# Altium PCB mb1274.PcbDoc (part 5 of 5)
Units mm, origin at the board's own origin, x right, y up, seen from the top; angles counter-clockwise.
Board outline 70 x 105 mm, 4 copper layers (Top Layer, Mid-Layer 1, Mid-Layer 2, Bottom Layer), stack 1.58 mm thick; 329 components, 271 nets, 1213 pads, 779 vias.
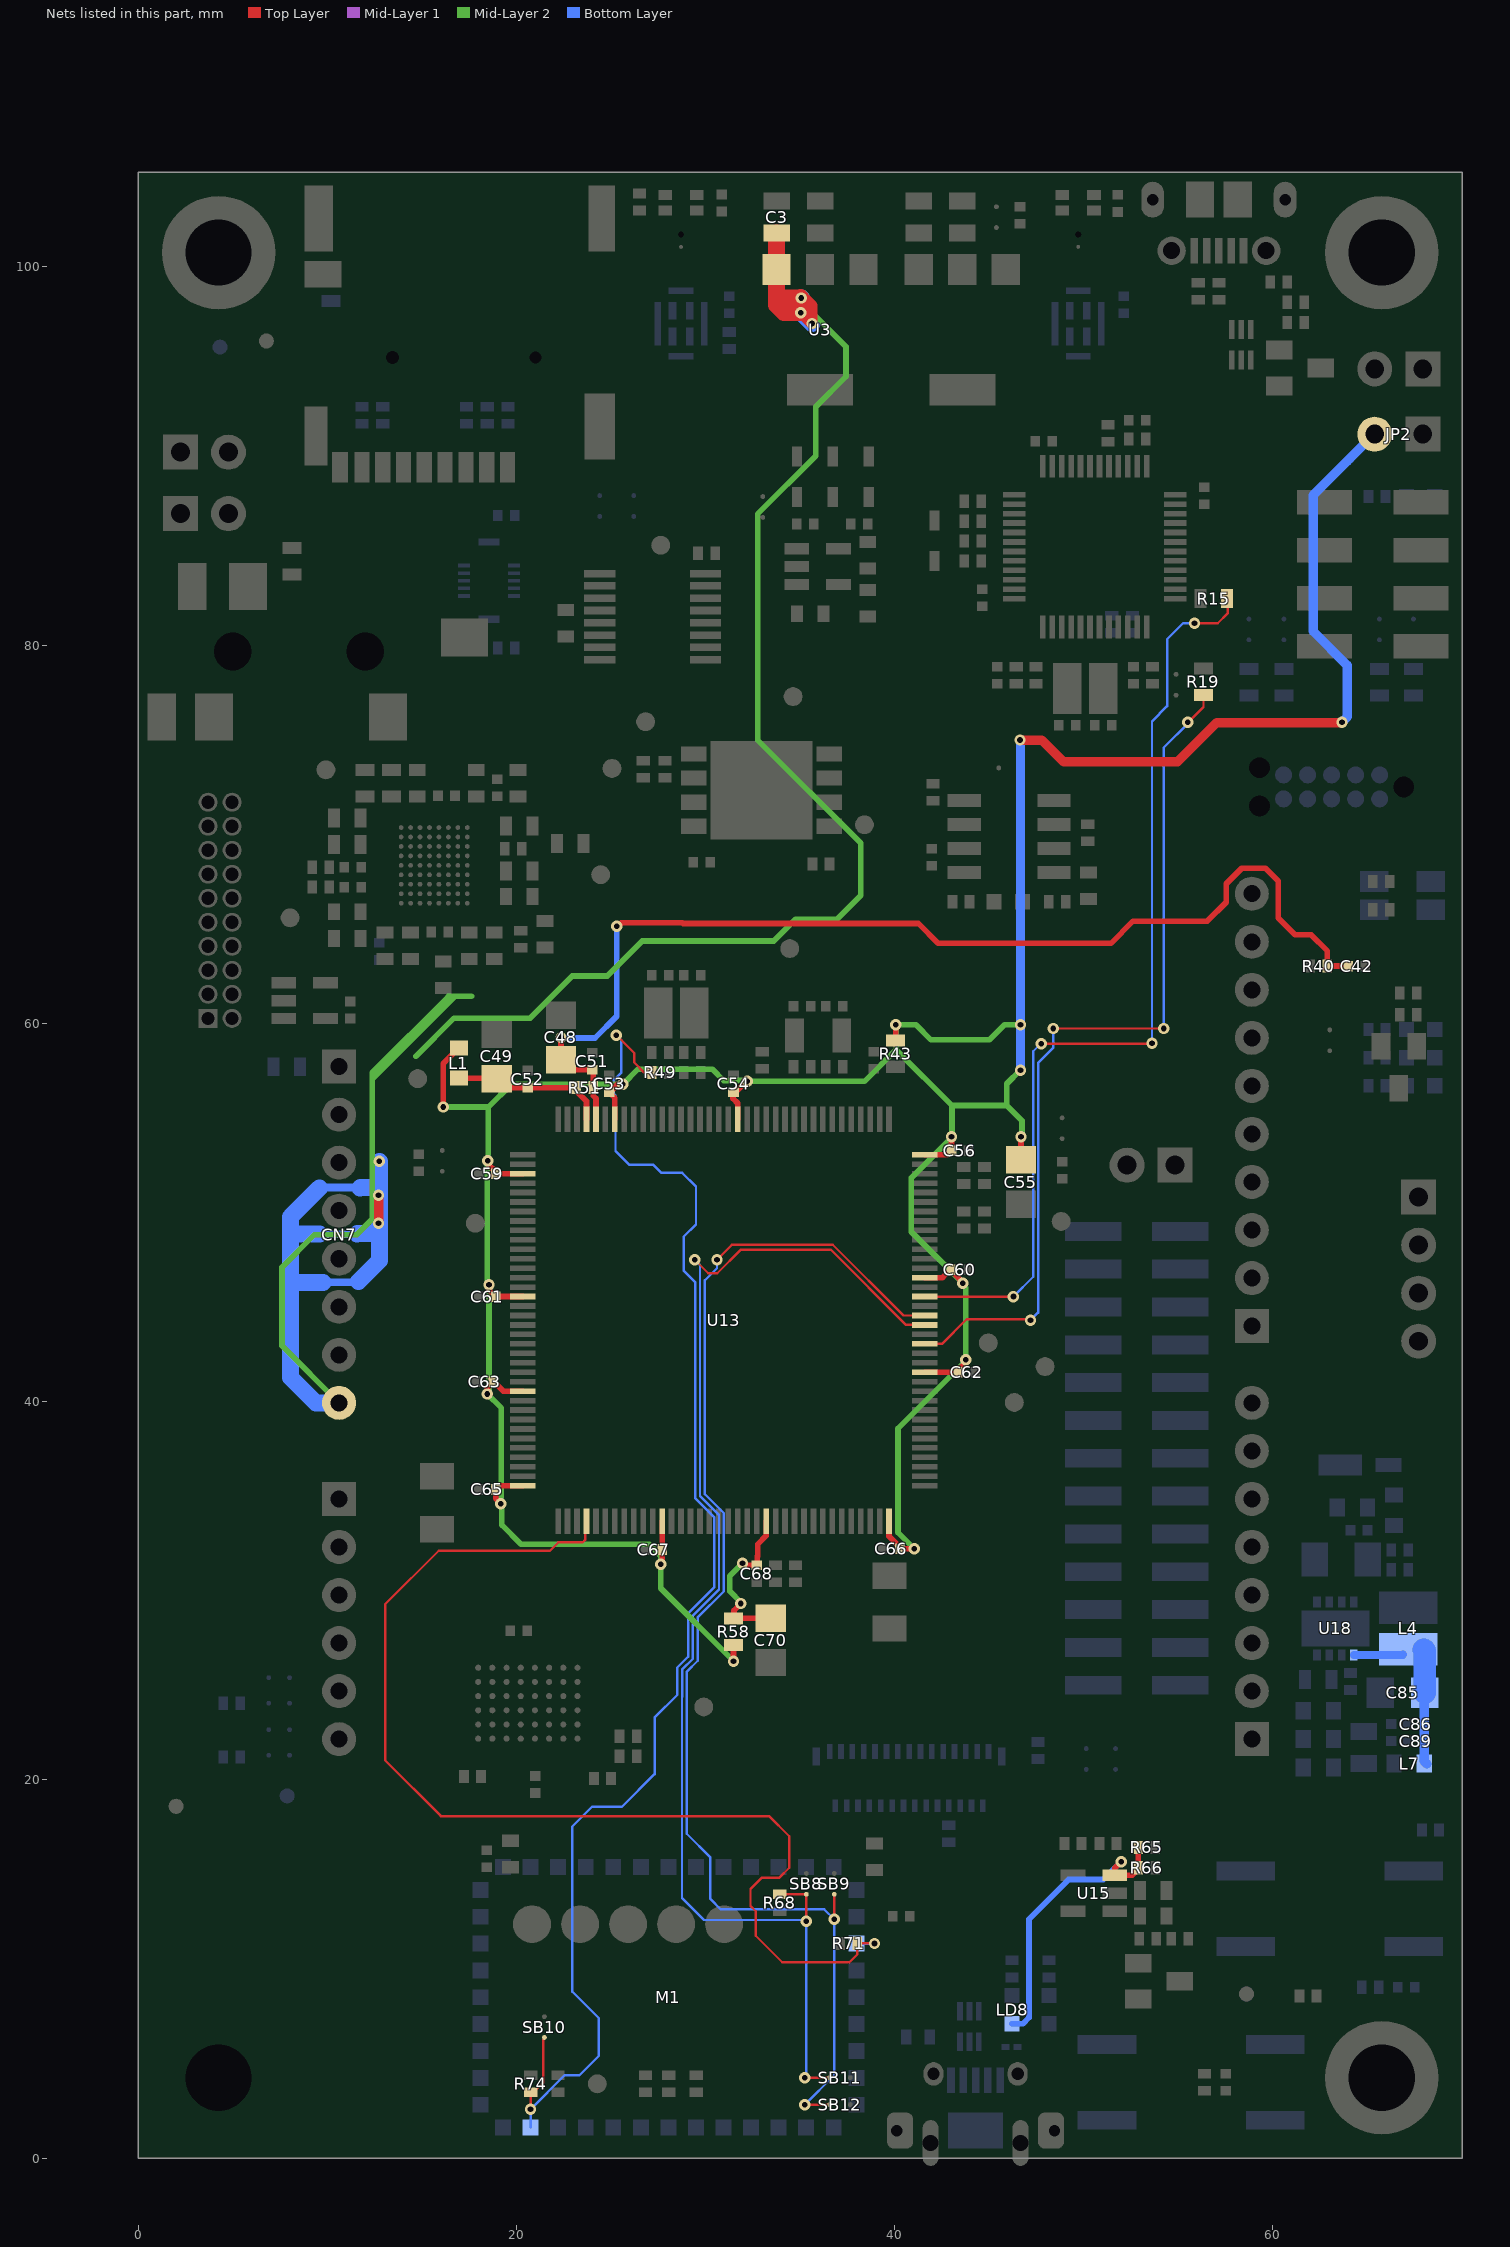
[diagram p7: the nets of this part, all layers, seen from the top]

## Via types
v1: diameter 0.6, hole 0.3, Top Layer to Bottom Layer, tented both sides, 574 vias
v2: diameter 0.4, hole 0.2, Top Layer to Bottom Layer, tented both sides, 125 vias
v3: diameter 0.8, hole 0.4, Top Layer to Bottom Layer, tented both sides, 49 vias
v4: diameter 0.3, hole 0.15, Top Layer to Bottom Layer, tented both sides, 31 vias

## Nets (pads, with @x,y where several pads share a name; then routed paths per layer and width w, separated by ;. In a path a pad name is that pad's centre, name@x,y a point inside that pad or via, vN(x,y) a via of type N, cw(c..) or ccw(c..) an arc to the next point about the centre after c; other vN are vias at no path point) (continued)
VBUS_OVRCR: LD8.2 R65.2 R66.1 U15.3 | length 15.3
  Top Layer w0.3: v1(51.975,15.675) 51.625,15.325 U15.3@51.625,14.95 52.55,14.95 R66.1@52.7,15.1 ; R66.1@52.875,15.475 R65.2@52.875,16.425
  Bottom Layer w0.3: LD8.2@46.2,7.1 46.775,7.1 47.1,7.425 47.1,12.625 49.2,14.725 51.025,14.725 v1(51.975,15.675)
VCP_RX: R19.1 U13.124 | length 46.5
  Top Layer w0.127: U13.124@41.575,43.05 42.5,43.05 43.8,44.35 47.129,44.35 v1(47.177,44.302) ; v1(48.375,59.725) v1@54.2,59.725 ; v1@55.525,75.925 56.325,76.725 R19.1@56.325,77.35
  Bottom Layer w0.127: v1(47.177,44.302) 47.579,44.704 47.579,57.904 48.375,58.7 v1(48.375,59.725) ; v1@54.225,59.625 v1(54.225,59.725) 54.225,74.575 v1@55.55,75.9
  other v1: 55.5,75.925
VCP_TX: R15.1 U13.129 | length 50.9
  Top Layer w0.127: U13.129@41.575,45.55 v1(46.275,45.55) ; v1(47.75,58.925) 53.575,58.925 v1(53.6,58.95) ; v1(55.85,81.15) 57.075,81.15 57.6,81.675 R15.1@57.6,82.55
  Bottom Layer w0.127: v1(46.275,45.55) 47.325,46.6 47.325,58.525 47.725,58.925 v1(47.75,58.925) ; v1(53.6,58.95) 53.6,75.966 54.404,76.77 54.404,80.304 55.25,81.15 v1(55.85,81.15)
VDD_MCU: C53.2 C54.2 C55.1 C56.2 C59.2 C60.2 C61.2 C62.2 C63.2 C65.2 C66.2 C67.2 JP2.2 L1.1 R43.2 R58.1 U13.17 U13.30 U13.39 U13.52 U13.62 U13.72 U13.84 U13.108 U13.121 U13.131 U13.144 | length 197.1
  Top Layer w0.3: v1(16.125,55.575) 16.125,57.875 L1.1@16.95,58.7 ; v1(18.45,40.4) 18.45,40.725 C63.2@18.775,41.05 ; v1(18.476,52.727) 18.476,52.574 18.9,52.15 C59.2@18.9,52.05 ; v1(18.55,46.175) 18.55,45.9 C61.2@18.9,45.55 ; C63.2@18.875,40.975 19.3,40.55 U13.62@20.325,40.55 ; C59.2@18.875,52.05 U13.39@20.325,52.05 ; C65.2@18.9,35.35 C65.2@18.9,35.325 ; C61.2@18.925,45.575 18.95,45.55 U13.52@20.325,45.55 ; v1(19.175,34.6) 18.9,34.875 C65.2@18.9,35.325 ; U13.72@20.325,35.55 19.525,35.55 19.125,35.55 C65.2@18.9,35.325 ; C53.2@24.9,56.35 24.927,56.35 25.352,56.775 v1(25.625,56.775) ; C53.2@24.95,56.3 25.2,56.05 U13.30@25.2,54.925 ; v1(27.625,31.4) 27.7,31.475 C67.2@27.7,32.175 U13.84@27.7,33.675 ; C54.2@31.45,56.35 31.45,56.025 31.7,55.775 U13.17@31.7,54.925 ; v1(31.475,26.275) R58.1@31.475,27.125 ; C54.2@31.475,56.35 31.575,56.35 32.152,56.927 v1(32.202,56.927) ; U13.108@39.7,33.675 39.7,32.875 C66.2@40.2,32.375 ; R43.2@40.05,59.1 v1(40.05,59.925) ; C66.2@40.275,32.225 v1(41.025,32.225) ; U13.121@41.575,41.55 C62.2@43.325,41.55 ; U13.131@41.575,46.55 42.525,46.55 C60.2@42.925,46.95 ; U13.144@41.575,53.05 42.775,53.05 C56.2@42.975,53.25 ; C60.2@43,46.975 43,46.9 43.602,46.298 v1(43.602,46.252) ; C56.2@43,53.25 43,54 v1(43.002,54.002) ; C62.2@43.35,41.55 43.35,41.675 43.825,42.15 43.804,42.15 v1(43.752,42.202) ; C55.1@46.675,52.775 v1(46.675,54) ; v1@63.625,75.9 v1(63.65,75.925)
  Top Layer w0.5: v1(46.625,74.975) 47.775,74.975 48.925,73.825 54.95,73.825 57.025,75.9 v1@63.625,75.9
  Mid-Layer 1 w0.3: v1@18.452,52.727 v1(18.476,52.727) ; v1@43.752,42.148 v1(43.752,42.202)
  Mid-Layer 2 w0.3: v1(16.125,55.575) 18.475,55.575 18.5,55.55 v1@18.5,52.775 ; v1(18.45,40.4) 19.2,39.65 v1@19.2,34.6 ; v1@18.475,40.45 18.55,40.525 v1(18.55,46.175) ; v1(18.476,52.727) 18.448,52.699 18.448,46.377 v1@18.6,46.225 ; 18.525,55.575 19.725,56.775 v1(25.625,56.775) 26.425,57.575 30.35,57.575 30.95,56.975 v1@32.175,56.975 ; v1@19.225,34.6 19.225,33.475 20.25,32.45 27.025,32.45 27.625,31.85 v1(27.625,31.4) 27.625,30.125 v1(31.475,26.275) ; v1(32.202,56.927) 38.402,56.927 40.075,58.6 ; v1(40.05,59.925) 41.125,59.925 41.925,59.125 45,59.125 45.8,59.925 v1(46.65,59.925) ; v1@40.075,59.9 40.075,58.6 ; v1(41.025,32.225) 40.175,33.075 40.175,38.575 v1@43.75,42.15 ; v1@43.025,54.075 43.025,55.65 ; v1@43.05,54 40.875,51.825 40.875,48.979 v1(43.602,46.252) ; v1@43.55,46.225 43.752,46.023 v1(43.752,42.202) ; v1(46.65,57.525) 45.925,56.8 45.925,55.65 ; v1@46.725,53.925 46.725,54.85 45.925,55.65 ; 40.075,58.6 43.025,55.65 ; 43.025,55.65 45.925,55.65
  Bottom Layer w0.3: v1(46.625,74.975) v1@46.65,74.95
  Bottom Layer w0.5: v1@46.65,57.575 v1(46.65,59.925) v1@46.65,74.95 ; v1(63.65,75.925) 63.925,76.2 63.925,78.925 62.125,80.725 62.125,87.925 64.05,89.85 ; 63.925,89.725 JP2.2@65.275,91.075
VDD_USB33: C68.2 C70.1 R58.2 U13.95 | length 8.9
  Top Layer w0.3: R58.2@31.475,28.5 31.525,28.55 C70.1@33.45,28.55 ; R58.2@31.475,28.525 31.5,28.55 31.5,28.95 31.85,29.3 v1(31.85,29.325) ; v1(31.952,31.451) v1(31.952,31.451) 31.95,31.35 C68.2@32.7,31.35 ; C68.2@32.725,31.4 32.725,31.825 ; 32.75,31.825 32.75,32.45 33.2,32.9 U13.95@33.2,33.675
  Mid-Layer 2 w0.3: v1@31.875,29.375 31.275,29.975 31.275,30.774 v1(31.952,31.451)
VDDA: C49.1 C52.2 L1.2 R51.2 U13.33 | length 8.2
  Top Layer w0.3: L1.2@16.95,57.1 18.975,57.1 C49.1@19.05,57.025 ; C49.1@18.95,57.075 19.425,56.6 C52.2@20.6,56.6 R51.2@23.15,56.6 ; R51.2@23.2,56.375 23.7,55.875 U13.33@23.7,54.925
VIN: C3.2 CN7.8 U3.3 | length 150.8
  Top Layer w0.3: U3.3@33.75,100.075 U3.3@33.875,99.95 ; v1@35.025,98.375 v1(35.05,98.35)
  Top Layer w0.5: v1(12.7,50.9) 12.725,50.875 v1@12.725,49.425
  Top Layer w0.6: v1(35.025,97.575) 35.6,97 v1(35.625,97) 35.625,97.95 v1@35.125,98.45
  Top Layer w0.9: U3.3@33.75,99.85 33.75,98.25 ; U3.3@33.75,100.075 C3.2@33.75,101.775 ; v1@35,97.575 34.15,97.575 33.75,97.975 33.75,98.25 ; v1(35.025,97.575) v1@35.025,98.35 ; v1@35.025,98.375 v1@35.025,98.35 ; v1(35.05,98.35) v1@35.025,98.35 ; 33.75,98.25 33.85,98.35 v1@35.025,98.35
  Mid-Layer 2 w0.3: CN7.8@10.62,39.93 7.6,42.95 7.6,47.1 9.325,48.825 11.55,48.825 12.375,49.65 12.375,57.05 ; 14.675,58.25 16.7,60.275 20.725,60.275 22.95,62.5 24.8,62.5 26.65,64.35 33.6,64.35 34.75,65.5 36.941,65.5 38.2,66.759 38.2,69.525 32.75,74.975 32.75,86.925 35.825,90 35.825,92.6 37.425,94.2 37.425,95.775 35.625,97.575 v1(35.025,97.575) ; 17.625,61.425 16.75,61.425 ; 12.375,57.05 16.75,61.425 ; 12.375,57.05 12.375,57.4 16.4,61.425 16.75,61.425
  Bottom Layer w0.4: 9.575,48.85 11.575,48.85 12.35,48.85 12.375,48.875 v1@12.675,49.175 ; 9.575,51.292 9.6,51.317 11.742,51.317 ; 9.781,46.3 11.65,46.3 12.675,47.325 12.675,47.375 12.675,48.875 v1@12.675,49.175 ; v1@12.675,49.475 v1@12.675,49.175 ; v1(12.7,50.9) v1(12.7,49.425) 12.7,49.2 v1@12.675,49.175
  Bottom Layer w0.9: 9.575,48.85 8.05,48.85 ; 9.575,51.292 8.05,49.767 8.05,48.85 ; 9.781,46.3 8.05,46.3 ; CN7.8@10.62,39.93 9.395,39.93 8.05,41.275 8.05,46.3 ; 11.575,48.85 11.6,48.875 12.375,48.875 12.675,48.875 ; 11.65,46.35 12.675,47.375 12.75,47.45 12.75,51.317 ; 11.725,51.3 11.742,51.317 12.75,51.317 ; v1(12.75,52.7) 12.75,51.317 ; v1@35.05,97.575 v1(35.05,98.35) ; v1@35.075,98.35 35.075,97.55 v1(35.625,97) ; 8.05,46.3 8.05,48.85
VL: C85.1 C86.2 C89.2 L4.1 L7.2 U18.1 | length 8.5
  Bottom Layer w0.4: U18.1@64.275,26.6 66.85,26.6 L4.1@66.875,26.625
  Bottom Layer w0.5: C85.1@68,24.35 C86.2@68,22.95 C89.2@68,22.05 68,20.975 L7.2@68.125,20.85
  Bottom Layer w1.2: L4.1@67.975,26.875 68.025,26.825 C85.1@68.025,24.6
VREF+: C42.2 C48.1 C51.2 R40.2 R51.1 U13.32 | length 58.9
  Top Layer w0.3: C48.1@22.35,58.075 22.35,59.251 v1(22.351,59.252) ; C48.1@22.475,57.875 22.8,57.55 C51.2@24,57.55 ; C51.2@24.025,57.6 24.05,57.575 R51.1@24.05,56.6 ; R51.1@24.05,56.575 24.05,56.175 24.2,56.025 U13.32@24.2,54.925 ; v1@25.325,65.1 25.544,65.319 28.778,65.319 28.822,65.275 41.25,65.275 42.299,64.227 51.427,64.227 52.6,65.4 56.525,65.4 57.525,66.4 57.525,67.375 58.35,68.2 59.6,68.2 60.275,67.525 60.275,65.575 61.175,64.675 62.025,64.675 62.875,63.825 R40.2@62.875,63.025 C42.2@63.975,63.025
  Bottom Layer w0.3: v1@22.35,59.225 24.15,59.225 25.3,60.375 v1(25.3,65.125)
WIFI_DRDY: SB9.1 SB12.1 U13.127 | length 68.7
  Top Layer w0.127: v1(30.6,47.5) 31.388,48.288 36.723,48.288 40.461,44.55 U13.127@41.575,44.55 ; v1(35.25,2.825) SB12.1@36.55,2.825 SB12.1@36.575,2.825 ; v1(36.8,12.625) SB9.1@36.8,13.95
  Bottom Layer w0.127: v1(30.6,47.5) 30.6,47.05 29.955,46.405 29.955,35.104 30.96,34.099 30.96,29.957 29.579,28.576 29.579,27.8 29.58,27.799 29.58,26.293 29.008,25.721 29.008,24.28 29.004,24.276 29.004,17.146 30.25,15.9 30.25,13.7 30.8,13.15 36.275,13.15 v1(36.8,12.625) 36.8,4.375 v1(35.25,2.825)
WIFI_RST: M1.34 R49.2 R74.1 SB10.2 | length 75.8
  Top Layer w0.127: v1(20.74,2.575) 20.75,2.585 R74.1@20.75,3.475 20.9,3.475 21.425,4 21.425,6.25 ; v1(25.275,59.375) 26.225,58.425 26.225,57.925 26.75,57.4 R49.2@27.15,57.4
  Bottom Layer w0.127: M1.34@20.747,1.62 20.747,2.568 v1(20.74,2.575) 22.54,4.375 23.325,4.375 24.35,5.4 24.35,7.4 22.95,8.8 22.95,17.525 24,18.575 25.575,18.575 27.3,20.3 27.3,23.291 28.5,24.491 28.5,25.932 29.072,26.504 29.072,27.12 29.071,27.121 29.071,28.786 30.452,30.167 30.452,33.889 29.447,34.894 29.447,46.316 28.838,46.925 28.838,48.716 29.49,49.368 29.49,51.362 28.762,52.091 27.66,52.091 27.225,52.525 25.95,52.525 25.235,53.24 25.235,56.185 25.135,56.285 25.135,56.978 25.546,57.39 25.546,59.104 v1(25.275,59.375)
WIFI_SPI_CSN: R68.2 SB8.1 SB11.1 U13.126 | length 69.2
  Top Layer w0.127: v1(29.425,47.5) 30.14,46.785 30.619,46.785 31.868,48.034 36.618,48.034 40.602,44.05 U13.126@41.575,44.05 ; R68.2@33.925,13.95 SB8.1@35.325,13.95 v1(35.325,12.525) ; v1(35.25,4.25) SB11.1@36.55,4.25 SB11.1@36.575,4.25
  Bottom Layer w0.127: v1(29.425,47.5) 29.701,47.224 29.701,34.999 30.706,33.994 30.706,30.062 29.325,28.681 29.325,27.227 29.326,27.226 29.326,26.398 28.754,25.826 28.754,24.386 28.75,24.382 28.75,13.75 29.914,12.586 35.264,12.586 v1(35.325,12.525) 35.325,4.325 v1(35.25,4.25)
WIFI_WKUP: M1.16 R71.1 U13.76 | length 59.6
  Top Layer w0.127: U13.76@23.7,33.675 23.625,33.6 23.625,32.68 23.5,32.555 22.209,32.555 21.767,32.112 15.885,32.112 13.053,29.28 13.053,21.031 16.003,18.082 33.357,18.082 34.425,17.013 34.425,15.35 33.9,14.825 32.975,14.825 32.375,14.225 32.375,13.325 32.65,13.05 32.65,11.75 34.05,10.35 37.6,10.35 38.025,10.775 R71.1@38.025,11.35 38.926,11.35 v1(38.929,11.347)
  Bottom Layer w0.127: M1.16@37.974,11.34 38.922,11.34 v1(38.929,11.347)
pads on no net: CN1.11 CN1.12 CN1.13 CN1.14 CN1.NPTH1 CN1.NPTH2 CN5.5 CN5.7 CN5.MT1 CN5.MT2 CN10.MT1 CN10.MT2 CN11.7 CN11.8 CN11.9 CN11.11 CN11.12 CN11.13 CN12.8 CN12.9 CN12.11 CN12.13 CN12.14 CN12.15 CN12.16 CN12.17 CN12.18 CN16.MT1 CN16.MT2 CN17.11 CN17.12 H3.1 M1.18 M1.19 M1.23 M1.24 M1.25 M1.26 M1.27 M1.30 M1.31 M1.32 MIRE1.1 MIRE2.1 MIRE3.1 MIRE4.1 MIRE5.1 MIRE6.1 U1.6 U2.6 U6.4 U6.11 U6.14 U6.16 U6.17 U6.19 U6.21 U6.22 U6.40 U6.41 U6.42 U6.43 U6.45 U6.46 U9.9 U11.A6 U11.A8 U11.A9 U11.B4 U11.B5 U11.B6 U11.B7 U11.B8 U11.B9 U11.C4 U11.C5 U11.C6 U11.C7 U11.C8 U11.E1 U11.E5 U11.F4 U11.F5 U11.F6 U11.F8 U11.F9 U11.G4 U11.H2 U11.H3 U11.H4 U11.H5 U14.E3 U16.6 U16.7 U16.8 U17.6 U17.7 U17.8 U18.5 U19.5

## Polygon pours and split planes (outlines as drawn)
BLGND on Mid-Layer 1 "BLGND_L02_P036" (solid, remove dead copper, pour order 36): 69.75,33.05 65.775,33.05 61.975,33.05 61.6,32.675 61.475,32.55 61.475,28 61.475,26.7 62.025,26.15 63.575,24.6 63.575,24.275 63.575,22.05 64.075,21.55 64.275,21.35 64.8,21.35 65.875,21.35 66.65,22.125 67.6,23.075 68.95,23.075 69.75,23.075
GND on Mid-Layer 1 "GND_L02_P034" (solid, remove dead copper, pour order 34): 0,105 0,0 0.025,0.025 0.725,0.025 21.35,0.025 70,0.025 70,1.675 70,22.5 68.125,22.5 67.925,22.5 67.15,21.725 66.2,20.775 64.975,20.775 64.1,20.775 63.425,21.45 62.875,22 62.875,23.15 62.875,24.425 62.175,25.125 60.85,26.45 60.85,27.2 60.85,32.825 61.275,33.25 61.55,33.525 62.15,33.525 70,33.525 70,34.025 70,104.925 69.925,105
3V3_ST_LINK on Mid-Layer 2 "3V3_ST_LINK_L03_P032" (solid, remove dead copper, pour order 32): 47.2,92.025 46.65,92.025 46.25,91.625 46.225,91.6 46.225,90.05 46.225,89.85 46.525,89.55 47.525,88.55 50.4,88.55 56.525,88.55 56.625,88.65 56.75,88.775 56.75,89.1 56.75,89.25 56.35,89.65 53.975,92.025 51.875,92.025
3V3_ST_LINK on Mid-Layer 2 "3V3_ST_LINK_L03_P030" (solid, remove dead copper, pour order 30): 68.425,50.1 68.425,49.7 68.225,49.5 67.025,49.5 66.8,49.5 66.325,49.975 65.55,50.75 65.475,50.825 65.475,51.125 65.475,55.05 65.225,55.3 64.675,55.85 64.475,56.05 64.475,56.85 64.475,67.1 64.1,67.475 61.7,69.875 61.7,70.325 61.7,71.125 61.9,71.325 61.95,71.375 62.575,71.375 63.725,71.375 64.2,71.85 64.375,72.025 64.375,72.95 64.375,78.45 64.15,78.675 63.425,79.4 62.95,79.4 60.4,79.4 60.05,79.05 55.35,74.35 54,74.35 52.125,74.35 51.9,74.575 51.825,74.65 51.825,75.4 51.825,75.525 52.15,75.85 53,76.7 53,77.275 53,79.775 51.5,81.275 51.1,81.675 51.1,82.6 51.1,82.675 51.625,83.2 51.65,83.225 54.075,83.225 60.525,83.225 60.8,82.95 61,82.75 61,82.275 61,81.425 61.65,80.775 62.2,80.225 63.2,80.225 64.65,80.225 65.35,79.525 67.325,77.55 67.325,76.2 67.325,70.075 67.7,69.7 67.7,67.325 67.7,66.225 67.7,61.975 67.35,61.625 66.75,61.025 66.75,59.15 66.75,57.15 67.1,56.8 68.425,55.475 68.425,52.65
5V_ST_LINK on Mid-Layer 2 "5V_ST_LINK_L03_P028" (solid, remove dead copper, pour order 28): 42.65,70.85 42.25,70.85 42.05,70.65 41.95,70.55 41.95,69.925 41.95,69.075 42.2,68.825 43.575,68.825 45.25,68.825 45.8,69.375 47.4,70.975 47.4,71.65 47.4,71.975 47.675,72.25 49.7,74.275 52.125,76.7 52.125,79.8 51.125,80.8 50.2,81.725 50.2,82.7 50.2,83.1 50.8,83.7 50.875,83.775 51.925,83.775 60.65,83.775 60.9,84.025 61,84.125 61,87.125 61,87.8 60.8,88 59.3,88 49.375,88 49.025,87.65 48.5,87.125 48.5,83.375 48.5,81.2 49,80.7 49.625,80.075 49.625,77.975 49.625,77.175 49.375,76.925 43.3,70.85 43.225,70.85
5V_USB_CHARGER on Mid-Layer 2 "5V_USB_CHARGER_L03_P026" (solid, remove dead copper, pour order 26): 61.3,79.025 63.1,79.025 63.175,79.025 63.475,78.725 63.85,78.35 63.85,77.5 63.85,72.325 63.35,71.825 61.125,71.825 55.1,71.825 54.775,71.5 52.3,69.025 52.3,67.825 52.3,66.25 51.475,65.425 50.55,64.5 47.725,64.5 43.775,64.5 42.1,66.175 40.825,67.45 40.825,68.325 40.825,74.825 42.325,76.325 43.475,77.475 45.025,77.475 45.875,77.475 46.3,77.9 46.35,77.95 46.35,79.05 46.35,85.15 46.35,85.675 45.575,86.45 44.25,87.775 43.325,87.775 37.325,87.775 37.075,88.025 37.075,91.025 37.375,91.325 37.725,91.325 37.95,91.1 37.95,90.3 38.675,89.575 39.15,89.575 45.875,89.575 47.25,88.2 47.9,87.55 47.9,85.55 47.9,80.975 48.45,80.425 49.175,79.7 49.175,78.975 49.175,77.375 48.4,76.6 43.1,71.3 42.45,71.3 41.8,71.3 41.525,71.025 41.525,68.9 42.025,68.4 42.05,68.375 45.225,68.375 45.5,68.375 47.975,70.85 47.975,71.7 48.425,72.15 50.075,73.8 51.425,73.8 55.425,73.8 58.9,77.275 60.65,79.025 60.7,79.025
3V3_ST_LINK on Mid-Layer 2 "3V3_ST_LINK_L03_P024" (solid, remove dead copper, pour order 24): 43.375,78.275 43.375,82 43.6,82.225 44.35,82.975 44.35,84.425 44.35,85.025 44.175,85.2 42.8,85.2 37.6,85.2 37.475,85.325 37.15,85.65 37.15,86.575 37.15,86.825 37.45,87.125 39.975,87.125 44.1,87.125 45.075,86.15 45.75,85.475 45.75,84.575 45.75,78.2 45.6,78.05 45.55,78 44.5,78 43.65,78 43.5,78.15
5V_ARD on Mid-Layer 2 "5V_ARD_L03_P020" (solid, remove dead copper, pour order 20): 9.375,61.425 8.275,61.425 7.125,60.275 6.2,59.35 6.2,58.325 6.2,57.275 6.525,56.95 6.75,56.725 10.175,56.725 11.5,56.725 14.525,59.75 16.85,62.075 18.2,62.075 19.525,62.075 21.775,64.325 22.175,64.725 22.6,65.15 26.275,65.15 33.25,65.15 33.525,65.425 34.7,66.6 35.45,66.6 36.175,66.6 36.825,67.25 36.875,67.3 36.875,69.25 36.875,69.45 36.575,69.75 31.55,74.775 31.55,75.85 31.55,87.3 32.475,88.225 34.05,89.8 34.05,92 35.575,93.525 36.6,94.55 36.6,95.25 36.6,95.725 36.1,96.225 36.025,96.3 35.775,96.3 35.075,96.3 34.35,97.025 34.225,97.15 34.225,97.6 34.225,99.025 34.375,99.175 34.75,99.55 35.2,99.55 36.75,99.55 37.825,98.475 39.925,96.375 39.925,94.825 40.875,93.875 41.675,93.875 55.175,93.875 56.45,92.6 56.95,92.6 59.675,92.6 60.7,91.575 63.95,88.325 63.95,87.1 63.95,85.025 64.2,84.775 64.525,84.45 65.175,84.45 65.65,84.45 65.95,84.75 65.95,87.1 65.95,87.55 64.625,88.875 57.975,95.525 54.275,95.525 48.075,95.525 47.075,96.525 45.95,97.65 43.75,97.65 40.725,97.65 40.3,98.075 39.7,98.675 39.7,99.3 39.7,101.15 39.225,101.625 34.05,101.625 33.3,101.625 32.95,101.275 32.825,101.15 32.825,99.825 32.825,94.025 31.9,93.1 28.25,89.45 28.25,88.225 28.25,72.025 28.65,71.625 30,70.275 31.6,70.275 33.8,70.275 34.75,69.325 34.75,68 34.5,67.75 22.075,67.75 21.125,66.8 20.2,65.875 19.225,65.875 18.5,65.875 18.025,65.4 15.85,63.225 15.325,63.225 15.225,63.225 14.875,62.875 13.425,61.425 12.125,61.425
GND on Mid-Layer 2 "GND_L03_P018" (solid, remove dead copper, pour order 18): -0.025,6.45 -0.025,0.4 0.35,0.025 0.375,0 4.8,0 13.55,0 13.75,0.2 13.75,5.275 13.75,6.1 13.4,6.45 11.85,6.45
VDD_MCU on Mid-Layer 2 "VDD_MCU_L03_P006" (solid, remove dead copper, pour order 6): 32.925,30.85 32.5,30.425 32.5,29.775 32.5,29.125 32.75,28.875 33.35,28.275 33.35,27.825 33.35,25.775 32.775,25.2 32.25,24.675 31.25,24.675 27.45,24.675 26.65,25.475 22.8,29.325 20.95,29.325 17.075,29.325 16.325,30.075 15.475,30.925 15.475,34.325 15.475,43.525 16.175,44.225 17.4,45.45 17.4,50.15 17.4,53.4 15.95,54.85 15.75,55.05 15.75,55.7 16.25,56.2 16.35,56.2 17.625,56.2 18.625,56.2 19.525,57.1 19.575,57.1 23.1,57.1 25.15,57.1 25.725,57.675 26.4,58.35 28.8,58.35 36.875,58.35 38.475,59.95 39.075,60.55 43.625,60.55 47.5,60.55 47.95,60.1 48.275,59.775 48.275,55.075 48.275,54.125 47.775,53.625 47.625,53.475 44.45,53.475 42.85,53.475 42.075,52.7 41.25,51.875 41.25,50.6 41.25,49.225 42.175,48.3 45.35,45.125 45.35,44.275 45.35,41.65 44.675,40.975 44.05,40.35 44.05,39.3 44.05,30.975 43.475,30.4 42.9,29.825 39.175,29.825 38,29.825 36.975,30.85
5V_USB_FS on Mid-Layer 2 "5V_USB_FS_L03_P002" (solid, remove dead copper, pour order 2): 62.2,8.85 60.225,6.875 54.625,6.875 52,6.875 47.325,2.2 47.325,0.8 47.95,0.175 48,0.125 54.85,0.125 69.9,0.125 69.85,0.175 69.85,3.275 69.85,78.525 67.275,81.1 63.575,84.8 63.575,86.05 63.575,88.05 62.85,88.775 59.525,92.1 57.325,92.1 56.35,92.1 56.275,92.1 54.85,93.525 53.675,93.525 39.55,93.525 38.15,92.125 38.15,90.875 38.15,90.725 38.625,90.25 38.9,89.975 40.125,89.975 43.825,89.975 45.375,91.525 46.25,92.4 47.8,92.4 54.15,92.4 55.65,90.9 58,88.55 59.175,88.55 60.875,88.55 61.325,88.1 61.7,87.725 61.7,87.075 61.7,81.625 62.45,80.875 62.675,80.65 64.925,80.65 64.95,80.65 66.85,78.75 67.9,77.7 67.9,71.7 67.9,70.95 68.225,70.625 68.225,67 68.125,66.9 68.125,64.675 68.125,61.5 67.525,60.9 67.25,60.625 67.25,59.45 67.25,57.425 67.95,56.725 68.7,55.975 68.7,52.925 68.7,48.875 67.525,47.7 66.25,46.425 65.7,45.875 65.625,45.8 65.625,39 65.625,35 66.875,33.75 68.55,32.075 68.55,31.4 68.55,30.35 68,29.8 67.675,29.475 67.675,28.725 67.675,20.7 67.675,14.35 65.1,11.775
3V3 on Mid-Layer 2 "3V3_L03_P004" (solid, remove dead copper, pour order 4): 226 vertices, not listed, extent 0.05,0.125 70,104.975
5V on Mid-Layer 2 "5V_L03_P008" (solid, remove dead copper, pour order 8): 48.5,14.984 48.5,13.025 48.5,12.2 49.725,10.975 50.55,10.975 52.698,13.123 52.698,13.85 54.349,15.501 54.349,16.275 54.9,16.825 58.825,16.825 63.975,16.825 65.3,18.125 65.3,20.7 65.3,31.65 65.55,31.9 66.35,32.7 66.35,33.325 66.35,33.75 66.1,34 65.25,34.85 65.25,35.85 65.25,46.125 65.6,46.475 66.375,47.25 66.375,49.15 65.5,50.025 64.95,50.575 64.95,52.45 64.95,54.875 64.6,55.225 64.05,55.775 64.05,56.4 64.05,66.8 61.5,69.35 59.55,71.3 56.1,71.3 55.425,71.3 53.125,69 53.025,68.9 53.025,67.95 53.025,65.975 51.875,64.825 50.875,63.825 48.5,63.825 43.2,63.825 42.125,64.9 40.35,66.675 40.35,67.75 40.35,75.15 41.725,76.525 42.85,77.65 42.85,78.475 42.85,83.425 43.375,83.95 43.5,84.075 43.5,84.4 43.5,84.625 43.275,84.85 43.25,84.825 42.725,84.825 42.5,84.825 42,84.325 38.95,81.275 38.95,70.45 38.95,64.225 37.975,63.25 37.95,63.225 35.825,63.225 34.125,61.525 30.875,61.525 23.275,61.525 22.625,60.875 21.275,59.525 20.475,59.525 17.4,59.525 14.175,56.3 14.1,56.225 14.1,52.15 14.1,49.1 13.475,48.475 10.225,48.475 10.125,48.475 9.65,48 9.175,47.525 9.175,44.275 9.925,43.525 9.975,43.475 11.475,43.475 14.725,43.475 15.6,44.35 16.975,45.725 16.975,46.725 16.975,53.4 16.4,53.975 15.5,54.875 15.5,55.55 15.5,55.95 15.975,56.425 16.025,56.475 16.775,56.475 18.475,56.475 19.15,57.15 19.35,57.35 19.725,57.35 24.775,57.35 25.425,58 26.2,58.775 27.025,58.775 36.4,58.775 37.725,60.1 38.75,61.125 40.2,61.125 48.025,61.125 48.55,60.6 49,60.15 49,58.325 49,54.7 50.775,52.925 54.775,48.925 54.775,47.75 54.775,33.425 55.55,32.65 55.875,32.325 60.05,32.325 60.375,32.325 61.7,31 63.15,29.55 63.15,20.95 63.15,19.25 62.6,18.7 62.5,18.6 61.45,18.6 61.025,18.6 60.625,19 60.45,19.175 60.45,20 60.45,20.55 60.9,21 61.1,21.2 61.1,22.425 61.1,22.525 59.725,23.9 57.34,23.9
VIN on Mid-Layer 2 "VIN_L03_P010" (solid, remove dead copper, pour order 10): 10.65,42.15 14.1,42.15 14.7,41.55 14.775,41.475 14.775,39.25 14.775,38.775 13.975,37.975 13.875,37.875 9.25,37.875 8.45,37.875 7,39.325 6.825,39.5 6.825,44.325 6.825,46.825 7.8,47.8 8.975,48.975 9.675,48.975 11.5,48.975 11.55,49.025 12.125,49.6 12.125,49.925 12.125,56.65 15.15,59.675 17.05,61.575 19.65,61.575 19.9,61.575 20.7,62.375 22.875,64.55 26.1,64.55 33.5,64.55 34.65,65.7 35.125,66.175 35.825,66.175 36.425,66.175 37.275,67.025 37.375,67.125 37.375,69.175 37.375,69.5 36.425,70.45 31.975,74.9 31.975,76.5 31.975,86.9 34.425,89.35 34.425,91.8 36.45,93.825 37.075,94.45 37.075,95.225 37.075,95.75 36.65,96.175 36.175,96.65 35.525,96.65 35.275,96.65 34.825,97.1 34.55,97.375 34.55,98.125 34.55,98.775 34.875,99.1 34.975,99.2 35.875,99.2 36.4,99.2 37.15,98.45 39.5,96.1 39.5,93.95 36.725,91.175 36.725,85.975 34,83.25 34,75.55 35.325,74.225 38.65,70.9 38.65,65.225 37.725,64.3 37.225,63.8 36,63.8 35.575,63.8 33.775,62 27.55,62 22.85,62 22.125,61.275 20.85,60 18.575,60 17.225,60 16.45,59.225 13.625,56.4 13.625,54.575 13.625,49.275 13.025,48.675 10.825,48.675 9.8,48.675 8.95,47.825 8.85,47.725 8.85,47.3 8.85,45 8.85,43.6 9.35,43.1 10.3,42.15 10.4,42.15
5V on Mid-Layer 2 "5V_L03_P012" (solid, remove dead copper, pour order 12): 39.1,72.1 39.075,72.1 37.175,74 37.175,78.525 37.175,84.025 38.025,84.875 43.425,84.875 43.6,84.7 43.65,84.65 43.65,84.35 43.65,83.075 43.4,82.825 42.575,82 42.575,81.075 42.575,77.65 40.825,75.9 39.575,74.65 39.575,72.1
VIN on Mid-Layer 2 "VIN_L03_P014" (solid, remove dead copper, pour order 14): 36.525,88.775 36.525,72.45 35.5,72.45 35.35,72.6 33.025,74.925 33.025,76.275 33.025,87.575 34.225,88.775 35.7,88.775
1V8 on Mid-Layer 2 "1V8_L03_P016" (solid, remove dead copper, pour order 16): 9.7,63.425 9.7,62.125 9.875,61.95 10.025,61.8 11.2,61.8 13,61.8 14.375,63.175 14.4,63.2 14.4,64.2 14.4,64.6 14.575,64.775 17.2,67.4 17.2,68.075 17.2,69.025 17,69.225 16.925,69.3 16.35,69.3 15.45,69.3 15.25,69.5 15.175,69.575 15.175,70.8 15.175,70.925 15.45,71.2 16.825,72.575 16.825,72.875 16.825,73.55 16.6,73.775 16.575,73.8 15.05,73.8 14.625,73.8 14.175,73.35 13.675,72.85 13.575,72.85 12.875,72.85 12,71.975 10.875,70.85 9.7,69.675 9.7,66.85
5V on Mid-Layer 2 "5V_L03_P022" (solid, remove dead copper, pour order 22): 41.55,101.55 40.825,101.55 40.4,101.125 40.325,101.05 40.325,100.45 40.325,98.875 40.7,98.5 40.95,98.25 41.575,98.25 46.225,98.25 46.55,97.925 48.45,96.025 50.375,96.025 57.7,96.025 58.25,96.025 58.85,95.425 66.45,87.825 66.45,86.5 66.45,82.8 67.025,82.225 68.925,80.325 69.925,80.325 69.925,83.775 69.925,85.175 69.925,89.425 69.675,89.675 67.875,89.675 67.1,89.675 66.975,89.8 66.75,90.025 66.75,90.175 66.75,92.325 66.65,92.425 66.125,92.95 66.125,93.275 66.125,93.7 66.05,93.775 60.6,99.225 59.7,99.225 54.75,99.225 54.2,98.675 53.25,97.725 52.3,97.725 50.075,97.725 49.75,98.05 46.25,101.55 45.05,101.55
GND on Bottom Layer "GND_L04_P042" (solid, remove dead copper, pour order 42): 0,105 0,104.525 0,0 0.225,0 70,0 70,1.1 70,105
GND on Top Layer "GND_L01_P040" (solid, remove dead copper, pour order 40): 0,105 0.625,105 70,105 70,0 0,0

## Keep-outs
Keep-Out Layer:
  the board outline again, w0.1
  text "BOARD OUTLINE" at 40.2,-16.825 h2
Multi-Layer:
  region: 17.45,17.375 0,17.375 0,0 17.45,0

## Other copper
Top Layer:
  pour cut-out: 5.625,62.075 5.275,61.725 5.275,60.4 6,59.675 13.65,59.675 13.9,59.925 13.9,60.925 12.775,62.05 12.2,62.05
  text "1" at 1.45,92.9 h1
  text "1" at 53.525,-11.325 h2
  text "PRIMARY SIDE" at 39.025,-16.825 h2
Mid-Layer 1:
  pour cut-out: 51.475,74.55 51.85,74.925 51.85,79.3 50.7,80.45 50.7,81.625 50.825,81.75 51.275,81.75 51.475,81.55 51.475,80.325 52.225,79.575 52.225,74.775 51.7,74.25 48.55,74.25 47.825,74.975 47.825,79.65 48.475,80.3 48.475,81.875 48.575,81.975 48.875,81.975 48.975,81.875 48.975,80.3 48.25,79.575 48.25,75.025 48.725,74.55
  pour cut-out: 34.675,62.2 33.85,61.375 33.85,56.975 35.275,55.55 35.275,53.8 35.125,53.65 34.775,53.65 34.775,53.675 34.625,53.825 34.625,55.6 33.45,56.775 33.45,61.625 34.4,62.575 37.6,62.575 38.4,61.775 38.4,56.85 37.95,56.4 37.45,55.9 37.45,53.85 37.25,53.65 36.75,53.65 36.625,53.775 36.625,55.875 37.875,57.125 37.875,61.675 37.35,62.2
  pour cut-out: 24.075,52.975 24,52.9 23.85,52.9 23.7,53.05 23.7,54.475 25.575,56.35 25.575,63.025 26.925,64.375 30.9,64.375 31.5,63.775 31.5,58.975 30.9,58.375 30.9,56.65 32.725,54.825 32.725,53.1 32.575,52.95 32.35,52.95 32.225,53.075 32.225,54.875 30.625,56.475 30.625,58.425 31.175,58.975 31.175,63.7 30.775,64.1 27.125,64.1 25.9,62.875 25.9,56.2 25.025,55.325 24.075,54.375
  text "2" at 2.95,92.9 h1
  text "2" at 53.525,-11.325 h2
  text "LAYER 2 (GND PLANE)" at 39.025,-16.825 h2
Mid-Layer 2:
  text "3" at 5.45,92.9 h1
  text "3" at 53.525,-11.325 h2
  text "LAYER 3 (VCC PLANE)" at 39.025,-16.825 h2
Bottom Layer:
  text "4" at 7.15,92.9 h1
  text "4" at 53.525,-11.325 h2
  text "SECONDARY SIDE" at 39.025,-16.825 h2
Multi-Layer:
  circle w0.2: c-11.201,-11.486 r3.442
  circle w0.2: c-11.201,-11.486 r1.922
  circle w0.2: c69.924,115.164 r3.442
  circle w0.2: c69.924,115.164 r1.922
  circle w0.2: c-13.251,109.188 r3.442
  circle w0.2: c-13.251,109.188 r1.922
  pour cut-out: 0.95,94.4 0.95,92.4 7.7,92.4 7.7,94.4
  lines w0.2: -19.22,109.125 -7.218,109.125 ; -17.17,-11.55 -5.168,-11.55 ; -13.251,103.092 -13.251,115.094 ; -11.201,-17.582 -11.201,-5.581 ; 63.955,115.1 75.957,115.1 ; 69.924,109.068 69.924,121.069

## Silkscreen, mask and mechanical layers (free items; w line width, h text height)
Top Overlay:
  drawing of 1503 lines, arcs and shapes, not listed
  text "1" at 61.35,100.375 h1.2
  text "USB" at 50.625,97.3 h1.2
  text "GND" at 67,96.25 h0.8
  text "ST_LINK" at 48.975,95.75 h1.2
  text "3V3" at 38.75,92.3 h1.2
  text "5V" at 31.95,92.175 h1.2
  text "MCU_PWR" at 57.3,90.8 h0.8
  text "PWR input" at 60.475,79.7 h1.2 r90
  text "1-2" at 59.325,77.25 h0.8
  text "5V_ST_LINK" at 61.975,77.25 h0.8
  text "3-4" at 59.325,75.75 h0.8
  text "5V_ARD" at 61.975,75.75 h0.8
  text "5-6" at 59.325,74.25 h0.8
  text "5V_USB_FS" at 61.975,74.25 h0.8
  text "AUDIO JACK" at 0.3,73.525 h1.05
  text "8MHz" at 50.375,73 h1.2
  text "5V_USB" at 61.975,72.1 h0.8
  text "7-8" at 59.325,72.075 h0.8
  text "_CHARGER" at 61.975,70.8 h0.8
  text "D15" at 60.725,66.25 h1.2
  text "D14" at 60.8,63.75 h1.2
  text "USB_FAULT" at 41.5,63.45 h1.2
  text "8MHz" at 26.625,63.2 h1.2
  text "AVDD" at 60.675,61.125 h1.2
  text "32.768KHz" at 38.1,59.85 h1.2
  text "1V8" at 5.775,58.1 h1.2
  text "GND" at 61.825,57.625 h1.2 r90
  text "D13" at 60.675,55.975 h1.2
  text "3V3" at 5.9,54.525 h1.2
  text "D12" at 60.675,53.55 h1.2
  text "NRST" at 4.75,51.825 h1.2
  text "D11" at 60.675,51.025 h1.2
  text "3V3" at 5.9,49.45 h1.2
  text "D10" at 60.675,48.475 h1.2
  text "5V" at 6.775,46.95 h1.2
  text "D9" at 60.675,45.95 h1.2
  text "PWR" at 14.05,44.95 h1.5 r90
  text "GND" at 5.75,44.4 h1.2
  text "D8" at 60.675,43.375 h1.2
  text "GND" at 5.75,41.875 h1.2
  text "VIN" at 6.675,39.35 h1.2
  text "D7" at 60.675,39.325 h1.2
  text "D6" at 60.675,36.8 h1.2
  text "A0" at 6.775,34.3 h1.2
  text "D5" at 60.675,34.25 h1.2
  text "D4" at 60.675,31.75 h1.2
  text "A1" at 7.325,31.725 h1.2
  text "MB1274E" at 45.025,29.7 h1.5
  text "D3" at 60.675,29.2 h1.2
  text "A2" at 6.85,29.175 h1.2
  text "A3" at 6.825,26.6 h1.2
  text "D2" at 60.7,26.575 h1.2
  text "D1" at 61.125,24.1 h1.2
  text "A4" at 6.775,24.075 h1.2
  text "www.st.com/stm32f4-discovery" at 3.1,22.2 h1.5 r90
  text "D0" at 61.1,21.55 h1.2
  text "A5" at 6.825,21.525 h1.2
  text "STM32F413H-DISCO" at 35.3,19.95 h1.5
  text "SILKSCREEN, (PRIMARY)" at 39.025,-16.825 h2
Bottom Overlay:
  drawing of 1498 lines, arcs and shapes, not listed
  text "USB" at 58.6,100.175 h1.2
  text "ST_LINK" at 60.025,98.45 h1.2
  text "MB1274E" at 33.5,88.1 h1.5 r270
  text "5V_PWR" at 69.55,86.075 h1
  text "TAG" at 53.575,70.975 h1.2 r270
  text "ST-LINK" at 69.1,63.525 h1.2
  text "ext Microphones" at 1,60.35 h1.2 r270
  text "LED3" at 64.1,59.125 h1.2
  text "LED4" at 64.05,57.6 h1.2
  text "LED5" at 64,56.05 h1.2
  text "ARD" at 69.25,54.75 h1.2
  text "DFU" at 64.825,44.925 h1.2 r270
  text "B_USER" at 62.975,17.1 h1.2
  text "WIFI 802.11 b/g/n" at 33.45,16.825 h1.5
  text "VCP_DEBUG" at 54.075,12.45 h1.2 r270
  text "VBUS OK" at 47.7,11.075 h0.8 r270
  text "VBUS OVRCR" at 45.775,11.05 h0.8 r270
  text "RESET" at 56.075,7.675 h1.2
  text "USB_OTG_FS" at 40.85,7.275 h1.2 r270
  text "SILKSCREEN, (SECONDARY)" at 80.725,-16.825 h2
Top Paste:
  text "SOLDER PASTE, (PRIMARY)" at 39.025,-16.825 h2
Bottom Paste:
  text "SOLDER PASTE, (SECONDARY)" at 39.025,-16.825 h2
Top Solder:
  text "SOLDER MASK, (PRIMARY)" at 39.025,-16.825 h2
Bottom Solder:
  text "SOLDER MASK, (SECONDARY)" at 39.025,-16.825 h2
Mechanical 2:
  circle w0.2: c-11.2,-11.486 r1.922
  circle w0.2: c-11.2,-11.486 r3.442
  circle w0.2: c69.925,115.164 r1.922
  circle w0.2: c69.925,115.164 r3.442
  circle w0.2: c-13.25,109.188 r1.922
  circle w0.2: c-13.25,109.188 r3.442
  lines w0.2: -19.219,109.125 -7.217,109.125 ; -17.169,-11.55 -5.167,-11.55 ; -13.25,103.092 -13.25,115.094 ; -11.2,-17.582 -11.2,-5.581 ; 63.956,115.1 75.958,115.1 ; 69.925,109.068 69.925,121.069
Drill Drawing:
  drawing of 226 lines, arcs and shapes, not listed
  text "IMPEDANCE TABLE" at 1.655,128.885 h1.25
  text "LAYER" at 3.51,125.405 h1.25
  text "WIDTH" at 15.143,125.405 h1.25
  text "Clearance" at 23.322,125.405 h1.25
  text "TOLERANCE" at 52.43,125.38 h1.25
  text "Differential Impedence" at 33.329,125.345 h1.25
  text "Layer1,4" at 3.51,123.144 h1.25
  text "90 OHM" at 34.787,122.888 h1.25
  text "6.1mil" at 14.863,122.814 h1.25
  text "8.9/18mil" at 22.765,122.838 h1.25
  text "PAIR" at 43.887,122.813 h1.25
  text "+/- 10%" at 53.319,122.763 h1.25
  text "LAYER STACK CONFIGURATION" at 100.309,122.083 h1.25
  text "55 OHM" at 37.275,120.325 h1.25
  text "Layer1,4" at 3.51,120.308 h1.25
  text "+/- 10%" at 52.913,120.308 h1.25
  text "5mil" at 14.863,120.249 h1.25
  text "8.7mil" at 24.515,120.249 h1.25
  text "4 LAYER BUILD" at 105.1,114.878 h1.25
  text "0.7mil" at 132.978,105.978 h1
  text "TOP LAYER" at 91.724,105.552 h1.25
  text "4.2mil" at 127.439,104.102 h1
  text "1.4mil" at 132.978,102.378 h1
  text "GND" at 91.724,102.175 h1.25
  text "44.9mil" at 127.689,98.577 h1
  text "1.4mil" at 132.989,95.477 h1
  text "VCC" at 91.724,95.377 h1.25
  text "4.2mil" at 127.439,93.877 h1
  text "0.7mil" at 132.989,92.327 h1
  text "BOTTOM LAYER" at 91.724,92.027 h1.25
  text "63mil" at 116.935,82.487 h1.25
  text "(plus soldermask thickness)" at 125.364,82.352 h1.25
  text "TOTAL BOARD THICKNESS: APPROX" at 84.395,82.338 h1.25
  text "Symbol" at 80.052,71.665 h1.83
  text "Hole Size" at 92.901,71.665 h1.83
  text "Plated" at 122.61,71.665 h1.83
  text "Count" at 135.459,71.665 h1.83
  text "Hole Length" at 150.695,71.665 h1.83
  text "Routed Path Length" at 179.135,71.665 h1.83
  text "0,150mm (5,91mil)" at 92.901,67.855 h1.52
  text "PTH" at 122.61,67.855 h1.52
  text "31" at 135.459,67.855 h1.52
  text "-" at 150.695,67.855 h1.52
  text "-" at 179.135,67.855 h1.52
  text "0,200mm (7,87mil)" at 92.901,64.045 h1.52
  text "PTH" at 122.61,64.045 h1.52
  text "125" at 135.459,64.045 h1.52
  text "-" at 150.695,64.045 h1.52
  text "-" at 179.135,64.045 h1.52
  text "0,300mm (11,81mil)" at 92.901,60.235 h1.52
  text "PTH" at 122.61,60.235 h1.52
  text "574" at 135.459,60.235 h1.52
  text "-" at 150.695,60.235 h1.52
  text "-" at 179.135,60.235 h1.52
  text "0,325mm (12,80mil)" at 92.901,56.425 h1.52
  text "NPTH" at 122.61,56.425 h1.52
  text "2" at 135.459,56.425 h1.52
  text "-" at 150.695,56.425 h1.52
  text "-" at 179.135,56.425 h1.52
  text "0,400mm (15,75mil)" at 92.901,52.615 h1.52
  text "PTH" at 122.61,52.615 h1.52
  text "49" at 135.459,52.615 h1.52
  text "-" at 150.695,52.615 h1.52
  text "-" at 179.135,52.615 h1.52
  text "0,600mm (23,62mil)" at 92.901,48.805 h1.52
  text "PTH" at 122.61,48.805 h1.52
  text "4" at 135.459,48.805 h1.52
  text "1,300mm (51,18mil)" at 150.695,48.805 h1.52
  text "0,700mm (27,56mil)" at 179.135,48.805 h1.52
  text "0,650mm (25,59mil)" at 92.901,44.995 h1.52
  text "PTH" at 122.61,44.995 h1.52
  text "2" at 135.459,44.995 h1.52
  text "0,850mm (33,47mil)" at 150.695,44.995 h1.52
  text "0,200mm (7,88mil)" at 179.135,44.995 h1.52
  text "0,650mm (25,59mil)" at 92.901,41.185 h1.52
  text "NPTH" at 122.61,41.185 h1.52
  text "1" at 135.459,41.185 h1.52
  text "-" at 150.695,41.185 h1.52
  text "-" at 179.135,41.185 h1.52
  text "C" at 79.313,40.931 h1.69
  text "0,700mm (27,56mil)" at 92.901,37.375 h1.52
  text "NPTH" at 122.61,37.375 h1.52
  text "1" at 135.459,37.375 h1.52
  text "-" at 150.695,37.375 h1.52
  text "-" at 179.135,37.375 h1.52
  text "B" at 79.313,37.121 h1.69
  text "0,700mm (27,56mil)" at 92.901,33.565 h1.52
  text "PTH" at 122.61,33.565 h1.52
  text "20" at 135.459,33.565 h1.52
  text "-" at 150.695,33.565 h1.52
  text "-" at 179.135,33.565 h1.52
  text "0,850mm (33,47mil)" at 92.901,29.755 h1.52
  text "NPTH" at 122.61,29.755 h1.52
  text "2" at 135.459,29.755 h1.52
  text "2,425mm (95,47mil)" at 150.695,29.755 h1.52
  text "1,575mm (62,01mil)" at 179.135,29.755 h1.52
  text "0,900mm (35,43mil)" at 92.901,25.945 h1.52
  text "PTH" at 122.61,25.945 h1.52
  text "34" at 135.459,25.945 h1.52
  text "-" at 150.695,25.945 h1.52
  text "-" at 179.135,25.945 h1.52
  text "1,000mm (39,37mil)" at 92.901,22.135 h1.52
  text "PTH" at 122.61,22.135 h1.52
  text "14" at 135.459,22.135 h1.52
  text "-" at 150.695,22.135 h1.52
  text "-" at 179.135,22.135 h1.52
  text "1,100mm (43,31mil)" at 92.901,18.325 h1.52
  text "NPTH" at 122.61,18.325 h1.52
  text "3" at 135.459,18.325 h1.52
  text "-" at 150.695,18.325 h1.52
  text "-" at 179.135,18.325 h1.52
  text "2,000mm (78,74mil)" at 92.901,14.515 h1.52
  text "NPTH" at 122.61,14.515 h1.52
  text "2" at 135.459,14.515 h1.52
  text "-" at 150.695,14.515 h1.52
  text "-" at 179.135,14.515 h1.52
  text "3,500mm (137,80mil)" at 92.901,10.705 h1.52
  text "NPTH" at 122.61,10.705 h1.52
  text "1" at 135.459,10.705 h1.52
  text "-" at 150.695,10.705 h1.52
  text "-" at 179.135,10.705 h1.52
  text "3,500mm (137,80mil)" at 92.901,6.895 h1.52
  text "PTH" at 122.61,6.895 h1.52
  text "3" at 135.459,6.895 h1.52
  text "-" at 150.695,6.895 h1.52
  text "-" at 179.135,6.895 h1.52
  text "868 Total" at 135.459,3.085 h1.52
  text "Slot definitions :" at 80.052,-0.597 h1.52
  text "Routed Path Length" at 106.282,-0.597 h1.52
  text "= Calculated from tool start centre position to tool end centre position." at 134.29,-0.597 h1.52
  text "Hole Length" at 106.282,-3.137 h1.52
  text "= Routed Path Length + Tool Size = Slot length as defined in the PCB layout" at 123.879,-3.137 h1.52
  text "FAB DRAWING & DRILL LEGEND" at 39.025,-16.825 h1.9
Mechanical 27:
  the board outline again, w0.1
  text "ASSEMBLY DRAWING, (PRIMARY)" at 38.625,-16.675 h1.9
Mechanical 30:
  the board outline again, w0.1
  text "ASSEMBLY DRAWING, (SECONDARY)" at 82.775,-16.475 h1.7

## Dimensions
0,0 to 0,105 on Drill Drawing
0,0 to 70,0 on Drill Drawing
